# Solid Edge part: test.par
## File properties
Title: Thrust bearing
Author: Abhinav Rai
Template: Normal.par
Last saved by: SOFT
Revision: 14
Application: Solid Edge
Accuracy: 0.99
Material: aluminum
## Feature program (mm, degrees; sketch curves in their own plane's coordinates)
sketch for "unnamed RevolvedProtrusion 1" plane through (0, 0, 0) normal (0, -1, 0) x-axis (1, 0, 0)
  line (47.625, 16.8036) -> (66.929, 16.8036)
  line (66.929, 16.8036) -> (73.025, 10.7076)
  line (73.025, 10.7076) -> (73.025, -12.0254)
  line (73.025, -12.0254) -> (66.929, -18.1214)
  line (66.929, -18.1214) -> (47.625, -18.1214)
  line (47.625, -18.1214) -> (47.625, -7.1994)
  line (61.5714, -7.1994) -> (47.625, -7.1994)
  line (61.5714, 5.8816) -> (61.5714, -7.1994)
  line (47.625, 5.8816) -> (61.5714, 5.8816)
  line (47.625, 5.8816) -> (47.625, 16.8036)
revolve "unnamed RevolvedProtrusion 1" add finite 360 deg
sketch for "unnamed RevolvedProtrusion 2" plane through (0, 0, 0) normal (1, 0, 0) x-axis (0, 1, 0)
  line (69.977, 13.7556) -> (73.0652, 13.7556)
  line (73.0652, 13.7556) -> (74.6125, 12.2083)
  line (74.6125, 12.2083) -> (74.6125, -13.4669)
  line (74.6125, -13.4669) -> (73.006, -15.0734)
  line (73.006, -15.0734) -> (69.977, -15.0734)
revolve "unnamed RevolvedProtrusion 2" add full turn 360 deg
sketch for "unnamed RevolvedProtrusion 3" plane through (0, 0, 0) normal (0, -1, 0) x-axis (1, 0, 0)
revolve "unnamed RevolvedProtrusion 3" add full turn 360 deg about sketch line (-54.9674, 10.1232) -> (-54.9674, -18.1214)
pattern "unnamed Pattern 1" of "unnamed RevolvedProtrusion 3"
pattern "unnamed Pattern 2"
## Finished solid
Body 1: solid body, 39 faces, 39 edges, 25 vertices.
  Faces by surface: torus 25, plane 6, cone 4, cylinder 4
  Edges by curve: circle 39
Bounding box of the edges (mm; curved faces can reach further): 149.225 x 149.225 x 34.925, from (-74.6125, -74.6125, -18.1214) to (74.6125, 74.6125, 16.8036).
Cylindrical faces by radius (mm): R47.625 x2, R61.5714 x1, R74.6125 x1
Conical faces (half-angle, radius in mm at the cone's reference point): 45 deg R66.929 x1, 45 deg R73.025 x1, 45 deg R73.0652 x1, 45 deg R74.6125 x1
Toroidal faces (ring radius, tube radius in mm): R-0.1023 r6.604 x25
Planar faces by outward normal: +z 3, -z 3
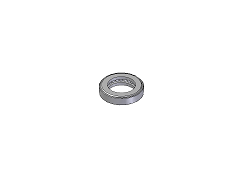
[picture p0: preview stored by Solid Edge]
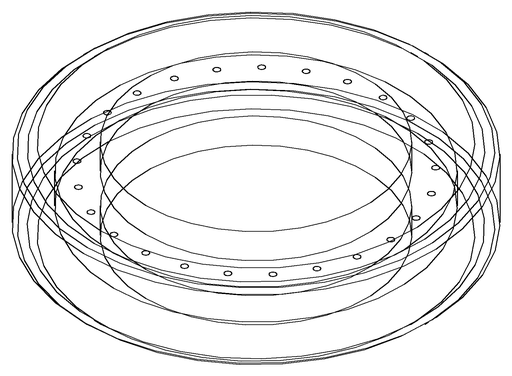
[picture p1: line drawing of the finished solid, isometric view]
